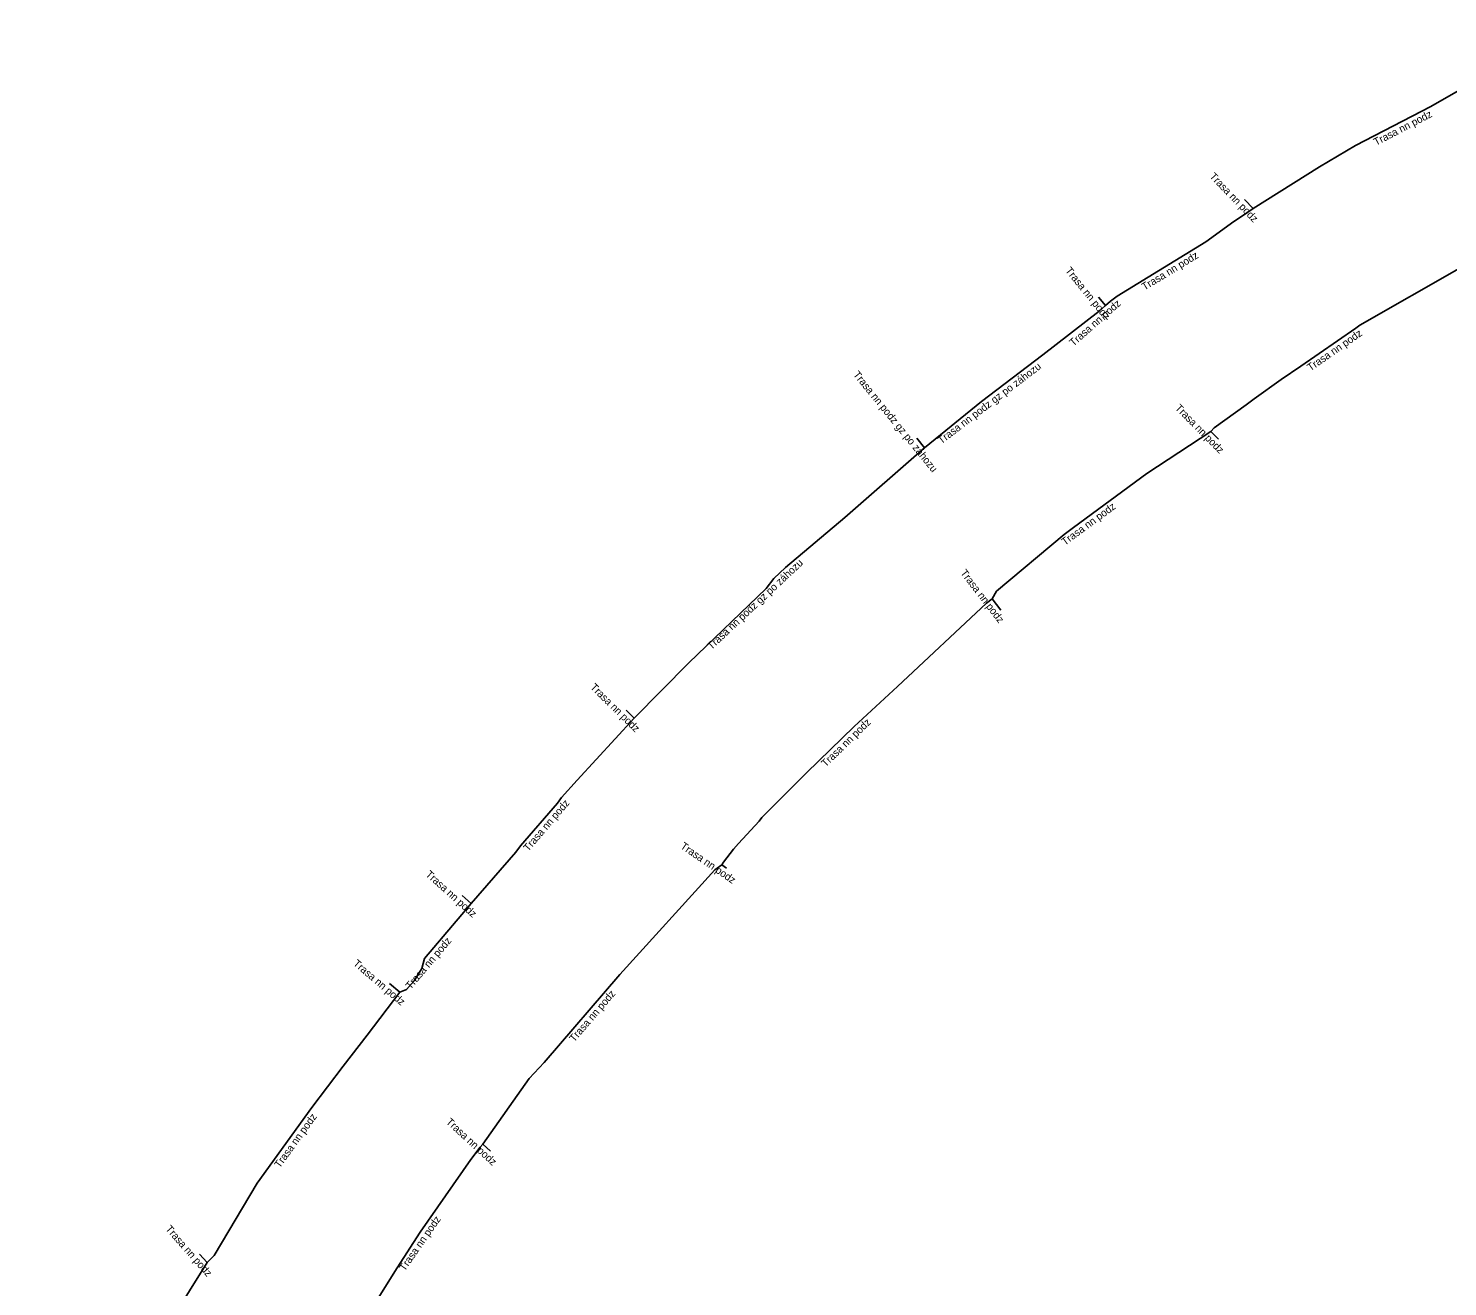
# Model space of a CAD drawing. Extents: x -756855 to -756032, y -1046964 to -1046550.
# Drawn here: x -756671.3 to -756576.6, y -1046723.5 to -1046639.6 of the extents above; entities that cross this region are included whole.
import ezdxf

# ---------------------------------------------------------------- set-up
doc = ezdxf.new("R2010")
doc.units = 0
doc.layers.add('Popiskový text - Ostatní atributy Trasy', color=7, linetype='Continuous')
doc.layers.add('Spojnice NN', color=7, linetype='Continuous')

msp = doc.modelspace()

# ---------------------------------------------------------------- linework, layer by layer
at = {"layer": 'Spojnice NN'}
for points in [[(-756567.99, -1046639.56), (-756571.01, -1046641.17), (-756573.89, -1046642.58), (-756577.74, -1046644.77), (-756582.77, -1046647.38), (-756585.17, -1046648.81), (-756589.61, -1046651.58)], [(-756589.61, -1046651.58), (-756590.18, -1046650.99)], [(-756589.61, -1046651.58), (-756590.46, -1046652.15), (-756590.9, -1046652.45), (-756592.77, -1046653.81), (-756598.68, -1046657.42), (-756599.12, -1046657.76), (-756599.46, -1046658.06)], [(-756592.43, -1046666.46), (-756592.21, -1046666.22), (-756590.08, -1046664.69), (-756589.54, -1046664.28), (-756587.73, -1046663), (-756586.42, -1046662.11), (-756582.76, -1046659.56), (-756582.49, -1046659.37), (-756575.69, -1046655.5), (-756574.11, -1046654.73)], [(-756599.46, -1046658.06), (-756599.92, -1046657.49)], [(-756599.87, -1046658.42), (-756603.63, -1046661.34), (-756607.74, -1046664.47), (-756611.54, -1046667.54)], [(-756599.46, -1046658.06), (-756599.87, -1046658.42)], [(-756611.54, -1046667.54), (-756612.06, -1046666.9)], [(-756607.03, -1046677.63), (-756606.74, -1046677.12), (-756602.21, -1046673.34), (-756601.59, -1046672.86), (-756596.69, -1046669.26), (-756592.43, -1046666.46)], [(-756592.43, -1046666.46), (-756591.923, -1046666.974)], [(-756611.54, -1046667.54), (-756616.86, -1046672.19), (-756620.81, -1046675.53), (-756621.6, -1046676.27), (-756622.11, -1046676.93), (-756627.27, -1046681.9), (-756630.91, -1046685.58)], [(-756625.07, -1046695.38), (-756624.95, -1046695.19), (-756624.28, -1046694.33), (-756623.96, -1046693.96), (-756622.57, -1046692.46), (-756622.39, -1046692.21), (-756619.42, -1046689.23), (-756616.24, -1046686.14), (-756613.35, -1046683.47), (-756607.4, -1046677.92), (-756607.03, -1046677.63)], [(-756606.45, -1046678.387), (-756607.03, -1046677.63)], [(-756630.91, -1046685.58), (-756631.45, -1046685.05)], [(-756630.91, -1046685.58), (-756634.71, -1046689.73), (-756635.77, -1046690.89), (-756636.04, -1046691.27), (-756638.49, -1046694.12), (-756638.82, -1046694.53), (-756641.8, -1046697.96)], [(-756641.01, -1046714.01), (-756637.93, -1046709.63), (-756636.92, -1046708.58), (-756631.87, -1046702.7), (-756625.52, -1046695.71), (-756625.07, -1046695.38)], [(-756624.747, -1046695.603), (-756625.07, -1046695.38)], [(-756641.8, -1046697.96), (-756642.39, -1046697.43)], [(-756641.8, -1046697.96), (-756644.9, -1046701.62), (-756645.08, -1046702.29), (-756645.59, -1046703.13), (-756646.1, -1046703.7), (-756646.55, -1046703.87)], [(-756646.55, -1046703.87), (-756647.23, -1046703.29)], [(-756659.41, -1046721.92), (-756658.94, -1046721.44), (-756656.07, -1046716.62), (-756652.42, -1046711.58), (-756650.34, -1046708.81), (-756648.74, -1046706.75), (-756646.55, -1046703.87)], [(-756648.65, -1046725.33), (-756648.11, -1046724.48), (-756646.73, -1046722.28), (-756645.19, -1046719.9), (-756641.81, -1046715.04), (-756641.2, -1046714.23), (-756641.01, -1046714.01)], [(-756641.01, -1046714.01), (-756640.502, -1046714.478)], [(-756659.41, -1046721.92), (-756659.91, -1046721.35)], [(-756671.34, -1046744.14), (-756670.71, -1046742.72), (-756669.18, -1046739.75), (-756667.8, -1046736.89), (-756664.71, -1046730.52), (-756663.69, -1046728.89), (-756663.19, -1046728.02), (-756662.95, -1046727.58), (-756659.41, -1046721.92)]]:
    msp.add_lwpolyline(points, dxfattribs=at)

# ---------------------------------------------------------------- texts
at = {"layer": 'Popiskový text - Ostatní atributy Trasy'}
for s, rotation, p in [('Trasa nn podz', 27.4242, (-756581.404, -1046647.404)), ('Trasa nn podz', 314.01224, (-756592.55, -1046649.473)), ('Trasa nn podz', 31.4178, (-756596.853, -1046657.065)), ('Trasa nn podz', 308.90414, (-756602.172, -1046655.734)), ('Trasa nn podz', 41.28471, (-756601.601, -1046660.806)), ('Trasa nn podz', 34.86575, (-756585.782, -1046662.457)), ('Trasa nn podz gz po záhozu', 309.09386, (-756616.326, -1046662.68)), ('Trasa nn podz gz po záhozu', 37.29135, (-756610.415, -1046667.324)), ('Trasa nn podz', 314.60718, (-756594.849, -1046664.933)), ('Trasa nn podz', 36.3045, (-756602.168, -1046674.091)), ('Trasa nn podz gz po záhozu', 43.12825, (-756625.757, -1046681.055)), ('Trasa nn podz', 307.4587, (-756609.171, -1046675.905)), ('Trasa nn podz', 315.53546, (-756633.882, -1046683.574)), ('Trasa nn podz', 44.17763, (-756618.136, -1046688.889)), ('Trasa nn podz', 49.31603, (-756637.978, -1046694.522)), ('Trasa nn podz', 325.3787, (-756627.868, -1046694.238)), ('Trasa nn podz', 318.06649, (-756644.871, -1046696.076)), ('Trasa nn podz', 49.73558, (-756645.833, -1046703.727)), ('Trasa nn podz', 319.53777, (-756649.707, -1046702.032)), ('Trasa nn podz', 49.34258, (-756634.913, -1046707.242)), ('Trasa nn podz', 54.08771, (-756654.565, -1046715.65)), ('Trasa nn podz', 317.34687, (-756643.511, -1046712.589)), ('Trasa nn podz', 311.25701, (-756662.225, -1046719.698)), ('Trasa nn podz', 55.18242, (-756646.229, -1046722.533))]:
    msp.add_text(s, height=0.5, rotation=rotation, dxfattribs=at).set_placement(p)

doc.saveas('drawing.dxf')
